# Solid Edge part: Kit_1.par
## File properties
Author: ahadarics
Last saved by: psaghy
Revision: 78
Sűrűség: 0,000 kg/m^3
Pontosság: 0,990
Username: ahadarics
Dokumentum tartalom típus: 0
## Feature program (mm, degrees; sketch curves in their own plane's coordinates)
base feature "unnamed BaseFeature 1"
sketch for "Furat_1" plane through (0, 0, 60) normal (0, 0, 1) x-axis (-1, 0, 0)
  hole centre (-110, 110) bore radius 8.647
hole "Furat_1" nominal diameter 20 finite  ThreadDepth = 25 mm
sketch for "unnamed Hole 1" plane through (0, 0, 60) normal (0, 0, 1) x-axis (-1, 0, 0)
  hole centre (-110, -110) bore radius 8.647
hole "unnamed Hole 1" finite
sketch for "unnamed Hole 2" plane through (0, 0, 60) normal (0, 0, 1) x-axis (-1, 0, 0)
  hole centre (110, -110) bore radius 8.647
hole "unnamed Hole 2" finite
sketch for "unnamed Hole 3" plane through (0, 0, 60) normal (0, 0, 1) x-axis (-1, 0, 0)
  hole centre (110, 110) bore radius 8.647
hole "unnamed Hole 3" finite
pattern "unnamed Pattern 1" of "Furat_1", "unnamed Hole 1", "unnamed Hole 2", "unnamed Hole 3"
sketch for "Furat_5" plane through (25, -134, 30) normal (0, -1, 0) x-axis (0, 0, -1)
  hole centre (0, 0) bore radius 15.1455
hole "Furat_5" nominal diameter 33.249 finite  ThreadDepth = 20 mm
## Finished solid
Body 1: solid body, 579 faces, 1318 edges, 769 vertices, 2 internal voids.
  Faces by surface: cylinder 179, plane 127, torus 97, spline 96, cone 63, sphere 17
  Edges by curve: circle 448, curve on surface 409, line 408, spline 30, intersection 16, ellipse 7
Bounding box of the edges (mm; curved faces can reach further): 270.000 x 270.000 x 135.000, from (-135, -135, 0) to (135, 135, 135).
Cylindrical faces by radius (mm): R1 x8, R2 x2, R2.0017 x1, R3 x14, R4 x38, R5 x1, R5.5 x1, R5.6 x1, R8 x40, R8.0041 x6, R8.0045 x6, R8.64 x4, R8.647 x4, R10 x8, R10.25 x4, R12 x1, R12.5 x1, R15.14 x1, R15.1455 x1, R16 x4, R20 x5, R22 x2, R23 x1, R24 x1, R25 x3, R25.4 x1, R25.4809 x1, R25.5 x2, R26 x8, R27.5 x1, R29 x1, R30 x2, R31 x2, R42.5 x1, R45 x1, R47 x1
Conical faces (half-angle, radius in mm at the cone's reference point): 1.6538 deg R26.75 x1, 3.5477 deg R27.7454 x1, 5.1705 deg R25.4 x1, 8.3742 deg R25.0032 x1, 13.2989 deg R26.1846 x1, 14.7738 deg R25.7787 x1, 15 deg R25.067 x2, 15 deg R27.433 x2, 16.6692 deg R26.1126 x1, 16.6692 deg R27.8874 x1, 25.0169 deg R29.31 x1, 30 deg R25.7887 x1, 45 deg R5.35 x1, 45 deg R5.75 x1, 45 deg R7.9 x1, 45 deg R8.64 x12, 45 deg R10.4 x8, 45 deg R15.14 x1, 45 deg R15.75 x8, 45 deg R16.5 x4, 45 deg R18.5 x4, 45 deg R30.5 x1, 45 deg R105 x6, 84 deg R25.4 x1, 84 deg R28.6 x1
Toroidal faces (ring radius, tube radius in mm): R2 r8 x8, R6 r2 x1, R7.0185 r3.0043 x6, R7.0186 r3.0044 x7, R7.0471 r3.0047 x5, R10 r8 x1, R11 r1 x8, R19 r1 x4, R22 r2 x1, R24 r2 x1, R25 r1 x4, R25.3 r0.3 x1, R25.3088 r0.3 x1, R26 r4 x1, R26.4279 r0.25 x1, R27 r0.6 x1, R27 r4 x1, R27.2464 r0.5 x1, R28 r4 x1, R29.8 r0.2 x1, R30 r4 x4, R34 r8 x8, R37.5 r5 x1, R44 r1 x1, R44.5 r2 x1, R46 r1 x1, R47 r2 x1, R51 r4 x8, R55 r8 x5, R100.8431 r4 x6, R109.1569 r4 x6
Spherical faces by radius (mm): R4 x5, R4.0564 x12
Planar faces by outward normal: +x 7, +y 11, +z 52, -x 4, -y 20, -z 9, oblique 24
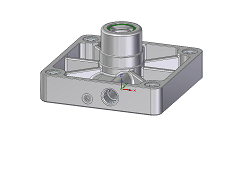
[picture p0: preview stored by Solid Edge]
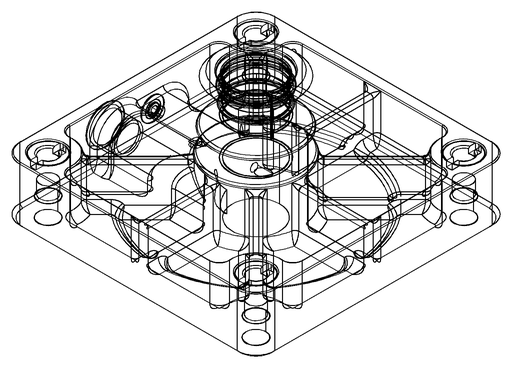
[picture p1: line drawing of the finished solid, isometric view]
